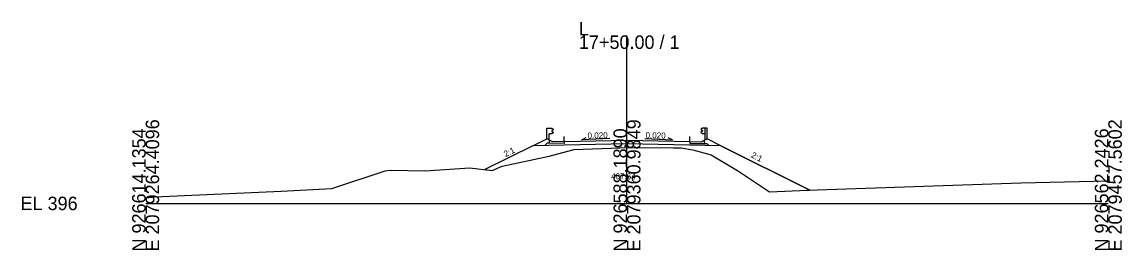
# Model space of a CAD drawing. Extents: x -26 to 10503, y -10 to 9546.
# Drawn here: x 974.3 to 1202.8, y 4990.3 to 5037.7 of the extents above; entities that cross this region are included whole.
import ezdxf

# ---------------------------------------------------------------- set-up
doc = ezdxf.new("R2010")
doc.units = 0
for name, color, linetype in [('Default', 7, 'Continuous'), ('Exist XS Center Line Elevation Label', 7, 'Continuous'), ('Exist XS Ground Line', 7, 'Continuous'), ('Old_Level_3', 7, 'Continuous'), ('Old_Level_58', 7, 'Continuous'), ('Old_Level_63', 7, 'Continuous'), ('Prop XS EOT Tick Mark', 7, 'Continuous'), ('Prop XS Finish Grade', 7, 'Continuous'), ('Prop XS Finish Grade CurbGutter', 7, 'Continuous'), ('Prop XS Finish Grade Earthwork', 7, 'Continuous'), ('Prop XS Finish Grade Pavement', 7, 'Continuous'), ('Prop XS Pvmt Edge Slope', 7, 'Continuous'), ('Prop XS SE Text', 7, 'Continuous'), ('Prop XS Side Slope Text', 7, 'Continuous'), ('Prop XS Subgrade CurbGutter', 7, 'Continuous'), ('Prop XS Subgrade Earthwork', 7, 'Continuous')]:
    doc.layers.add(name, color=color, linetype=linetype)

msp = doc.modelspace()

# ---------------------------------------------------------------- linework, layer by layer
at = {"layer": 'Default'}
msp.add_lwpolyline([(1109.59, 5011.58), (1111.23, 5011.59), (1113.65, 5011.11), (1117.5, 5010.13), (1123.19, 5006.68), (1129.59, 5002.4), (1137.47, 5002.73), (1137.99, 5002.75), (1119.48, 5012), (1100, 5012.39), (1080.42, 5012), (1070.48, 5007.03), (1072.01, 5006.84), (1074.05, 5007.77), (1083.83, 5009.83), (1087.71, 5010.86), (1089.01, 5011.19), (1098.49, 5011.56), (1100.05, 5011.64)], close=True, dxfattribs=at)
at = {"layer": 'Exist XS Ground Line'}
for p, q in [((1074.05, 5007.77), (1083.83, 5009.83)), ((1083.83, 5009.83), (1087.71, 5010.86)), ((1087.71, 5010.86), (1089.01, 5011.19)), ((1089.01, 5011.19), (1098.49, 5011.56)), ((1098.49, 5011.56), (1100.05, 5011.64)), ((1100.05, 5011.64), (1109.59, 5011.58)), ((1109.59, 5011.58), (1111.23, 5011.59)), ((1111.23, 5011.59), (1113.65, 5011.11)), ((1113.65, 5011.11), (1117.5, 5010.13)), ((1117.5, 5010.13), (1123.19, 5006.68)), ((1060.05, 5006.91), (1067.34, 5007.42)), ((1067.34, 5007.42), (1072.01, 5006.84)), ((1072.01, 5006.84), (1074.05, 5007.77)), ((1038.65, 5003.07), (1049.77, 5006.76)), ((1049.77, 5006.76), (1050.81, 5006.94)), ((1050.81, 5006.94), (1058.11, 5006.8)), ((1058.11, 5006.8), (1060.05, 5006.91)), ((1123.19, 5006.68), (1129.59, 5002.4)), ((1028.13, 5002.55), (1038.65, 5003.07)), ((1129.59, 5002.4), (1137.47, 5002.73)), ((1137.47, 5002.73), (1181.85, 5004.28)), ((1181.85, 5004.28), (1200, 5004.71)), ((1000, 5001.15), (1001.87, 5001.35)), ((1001.87, 5001.35), (1028.13, 5002.55))]:
    msp.add_line(p, q, dxfattribs=at)
at = {"layer": 'Old_Level_3'}
for p, q in [((1083.35, 5013.46), (1083.35, 5015.63)), ((1083.35, 5015.63), (1083.85, 5015.63)), ((1083.85, 5015.63), (1084.35, 5015.63)), ((1084.35, 5014.49), (1083.85, 5014.49)), ((1083.85, 5013.21), (1083.85, 5014.49)), ((1084.35, 5015.63), (1084.64, 5015.43)), ((1084.64, 5015.31), (1084.35, 5015.11)), ((1084.35, 5015.11), (1084.35, 5015.01)), ((1084.35, 5015.01), (1084.64, 5014.81)), ((1084.64, 5014.69), (1084.35, 5014.49)), ((1084.64, 5015.43), (1084.67, 5015.37)), ((1084.67, 5015.37), (1084.64, 5015.31)), ((1084.64, 5014.81), (1084.67, 5014.75)), ((1084.67, 5014.75), (1084.64, 5014.69)), ((1115.39, 5015.46), (1115.36, 5015.4)), ((1115.36, 5015.4), (1115.39, 5015.34)), ((1115.39, 5014.85), (1115.36, 5014.79)), ((1115.36, 5014.79), (1115.39, 5014.73)), ((1115.68, 5015.66), (1115.39, 5015.46)), ((1115.39, 5015.34), (1115.68, 5015.14)), ((1115.68, 5015.05), (1115.39, 5014.85)), ((1115.39, 5014.73), (1115.68, 5014.53)), ((1116.18, 5015.66), (1115.68, 5015.66)), ((1115.68, 5015.14), (1115.68, 5015.05)), ((1115.68, 5014.53), (1116.18, 5014.53)), ((1116.68, 5015.66), (1116.18, 5015.66)), ((1116.18, 5015.66), (1116.18, 5013.18)), ((1116.68, 5013.43), (1116.68, 5015.66))]:
    msp.add_line(p, q, dxfattribs=at)
at = {"layer": 'Old_Level_63'}
for p, q in [((1100, 5000), (1100, 5034.93)), ((1000, 5000), (1100, 5000)), ((1100, 5000), (1200, 5000))]:
    msp.add_line(p, q, dxfattribs=at)
at = {"layer": 'Prop XS EOT Tick Mark'}
for p, q in [((1086.95, 5012.88), (1086.95, 5013.88)), ((1113.05, 5012.88), (1113.05, 5013.88))]:
    msp.add_line(p, q, dxfattribs=at)
at = {"layer": 'Prop XS Finish Grade'}
for p, q in [((1080.42, 5012), (1083.35, 5013.46)), ((1083.93, 5013.17), (1083.35, 5013.46)), ((1116.07, 5013.13), (1116.65, 5013.42)), ((1119.48, 5012), (1116.65, 5013.42))]:
    msp.add_line(p, q, dxfattribs=at)
at = {"layer": 'Prop XS Finish Grade CurbGutter'}
for p, q in [((1084.62, 5012.83), (1083.93, 5013.17)), ((1086.95, 5012.88), (1084.62, 5012.83)), ((1113.05, 5012.88), (1115.38, 5012.79)), ((1115.38, 5012.79), (1116.07, 5013.13))]:
    msp.add_line(p, q, dxfattribs=at)
at = {"layer": 'Prop XS Finish Grade Earthwork'}
for p, q in [((1080.42, 5012), (1070.48, 5007.03)), ((1119.48, 5012), (1137.99, 5002.75))]:
    msp.add_line(p, q, dxfattribs=at)
at = {"layer": 'Prop XS Finish Grade Pavement'}
for p, q in [((1086.95, 5012.88), (1100, 5013.14)), ((1100, 5013.14), (1113.05, 5012.88))]:
    msp.add_line(p, q, dxfattribs=at)
at = {"layer": 'Prop XS Pvmt Edge Slope'}
for p, q in [((1083.43, 5012.53), (1082.94, 5012.05)), ((1083.93, 5012.52), (1083.43, 5012.53)), ((1116.07, 5012.46), (1116.57, 5012.46)), ((1116.57, 5012.46), (1116.98, 5012.05))]:
    msp.add_line(p, q, dxfattribs=at)
at = {"layer": 'Prop XS SE Text'}
for points in [[(1096.41, 5013.49), (1090.65, 5013.22), (1091.51, 5013.68)], [(1103.68, 5013.48), (1109.44, 5013.2), (1108.58, 5013.66)]]:
    msp.add_lwpolyline(points, dxfattribs=at)
at = {"layer": 'Prop XS Subgrade CurbGutter'}
for p, q in [((1083.93, 5012.52), (1083.93, 5013.17)), ((1086.95, 5012.46), (1083.93, 5012.52)), ((1086.95, 5012.88), (1086.95, 5012.46)), ((1113.05, 5012.88), (1113.05, 5012.46)), ((1113.05, 5012.46), (1116.07, 5012.46)), ((1116.07, 5012.46), (1116.07, 5013.13))]:
    msp.add_line(p, q, dxfattribs=at)
at = {"layer": 'Prop XS Subgrade Earthwork'}
for p, q in [((1100, 5012.39), (1080.42, 5012)), ((1119.48, 5012), (1100, 5012.39))]:
    msp.add_line(p, q, dxfattribs=at)

# ---------------------------------------------------------------- texts
at = {"layer": 'Exist XS Center Line Elevation Label'}
msp.add_text('407.64', height=1.25, rotation=360, dxfattribs=at).set_placement((1096.7, 5005.01))
at = {"layer": 'Old_Level_58'}
msp.add_text('Case1', height=0.04, dxfattribs=at).set_placement((1116.18, 5013.16))
at = {"layer": 'Old_Level_63'}
for s, p in [('L', (1090, 5034.93)), ('17+50.00 / 1', (1090, 5032.13)), ('EL 396', (974, 4998.6))]:
    msp.add_text(s, height=2.8, dxfattribs=at).set_placement(p)
for s, p in [('E 2079264.4096', (1002.8, 4990)), ('E 2079360.9849', (1102.8, 4990)), ('E 2079457.5602', (1202.8, 4990)), ('N 926614.1354', (1000, 4990)), ('N 926588.1890', (1100, 4990)), ('N 926562.2426', (1200, 4990))]:
    msp.add_text(s, height=2.8, rotation=90, dxfattribs=at).set_placement(p)
at = {"layer": 'Prop XS SE Text'}
for rotation, p in [(1.1458, (1091.81, 5013.48)), (358.8542, (1103.84, 5013.56))]:
    msp.add_text('0.020', height=1.25, rotation=rotation, dxfattribs=at).set_placement(p)
at = {"layer": 'Prop XS Side Slope Text'}
for rotation, p in [(26.5651, (1074.77, 5009.62)), (333.4349, (1125.66, 5009.64))]:
    msp.add_text('2:1', height=1.25, rotation=rotation, dxfattribs=at).set_placement(p)

doc.saveas('drawing.dxf')
